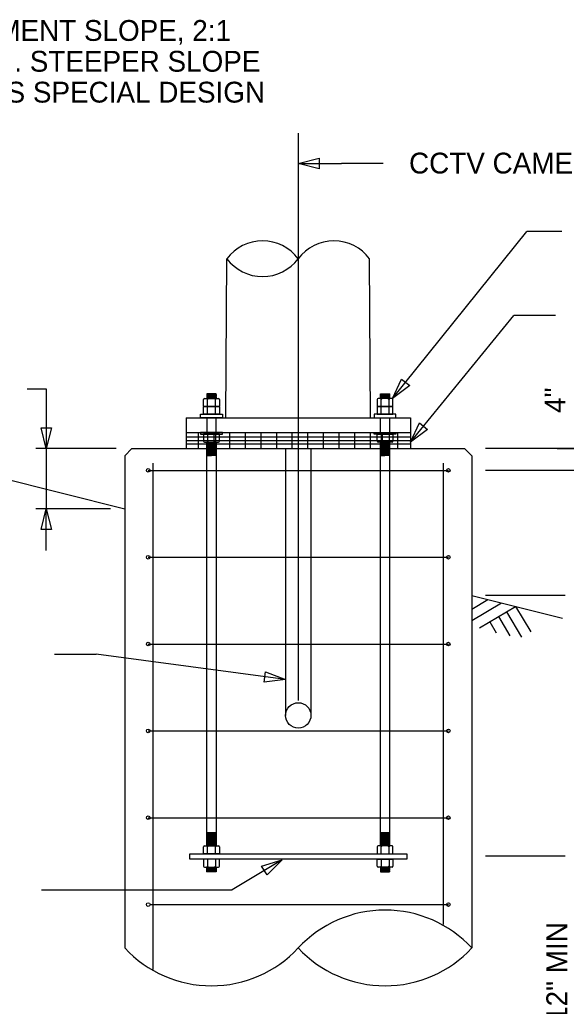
# Model space of a CAD drawing. Extents: x 1299104.6 to 1299141.4, y 239713.3 to 239735.3.
# Drawn here: x 1299108.96 to 1299112.11, y 239719.15 to 239724.83 of the extents above; entities that cross this region are included whole.
import ezdxf

# ---------------------------------------------------------------- set-up
doc = ezdxf.new("R2010")
doc.units = 0
for name, color, linetype in [('DIM TXT', 7, 'Continuous'), ('Level 3', 7, 'Continuous'), ('Level 4', 7, 'Continuous'), ('Level 7', 7, 'Continuous'), ('Level 8', 7, 'Continuous')]:
    doc.layers.add(name, color=color, linetype=linetype)

msp = doc.modelspace()

# ---------------------------------------------------------------- linework, layer by layer
at = {"layer": 'Level 3'}
for p, q in [((1299110.1458, 239722.5377), (1299110.1513, 239723.4544)), ((1299110.9791, 239722.5377), (1299110.9737, 239723.4544)), ((1299107.0626, 239722.6396), (1299109.5625, 239722.0146)), ((1299110.0397, 239722.6041), (1299110.0397, 239722.6443)), ((1299110.0853, 239722.6041), (1299110.0853, 239722.6443)), ((1299111.0397, 239722.6041), (1299111.0397, 239722.6443)), ((1299111.0853, 239722.6041), (1299111.0853, 239722.6443)), ((1299110.0397, 239722.5585), (1299110.0397, 239722.5988)), ((1299110.0853, 239722.5585), (1299110.0853, 239722.5988)), ((1299111.0397, 239722.5585), (1299111.0397, 239722.5988)), ((1299111.0853, 239722.5585), (1299111.0853, 239722.5988)), ((1299109.9166, 239722.5377), (1299111.2083, 239722.5377)), ((1299109.9166, 239722.5377), (1299109.9166, 239722.4544)), ((1299111.0884, 239722.5377), (1299111.0884, 239722.4544)), ((1299111.2083, 239722.5377), (1299111.2083, 239722.4544)), ((1299109.9166, 239722.4544), (1299111.2083, 239722.4544)), ((1299110.0397, 239722.4439), (1299110.0397, 239722.4037)), ((1299110.0853, 239722.4439), (1299110.0853, 239722.4037)), ((1299111.0397, 239722.4439), (1299111.0397, 239722.4037)), ((1299111.0853, 239722.4439), (1299111.0853, 239722.4037)), ((1299109.6041, 239722.3606), (1299109.5625, 239722.3189)), ((1299109.6041, 239722.3606), (1299111.5208, 239722.3606)), ((1299110.4896, 239722.3606), (1299110.4896, 239720.8247)), ((1299110.6354, 239722.3606), (1299110.6354, 239720.8247)), ((1299111.5208, 239722.3606), (1299111.5625, 239722.3189)), ((1299109.5625, 239722.3189), (1299109.5625, 239719.4856)), ((1299111.5625, 239722.3189), (1299111.5625, 239719.4856)), ((1299109.6979, 239722.2356), (1299111.4271, 239722.2356)), ((1299109.7265, 239719.361), (1299109.7265, 239722.2773)), ((1299111.3984, 239719.6215), (1299111.3984, 239722.2773)), ((1299109.6979, 239721.7356), (1299111.4271, 239721.7356)), ((1299111.5625, 239721.5146), (1299112.0854, 239721.3839)), ((1299109.6979, 239721.2356), (1299111.4271, 239721.2356)), ((1299109.6979, 239720.7356), (1299111.4271, 239720.7356)), ((1299109.6979, 239720.2356), (1299111.4271, 239720.2356)), ((1299110.0397, 239720.0273), (1299110.0397, 239720.0675)), ((1299110.0853, 239720.0273), (1299110.0853, 239720.0675)), ((1299111.0397, 239720.0273), (1299111.0397, 239720.0675)), ((1299111.0853, 239720.0273), (1299111.0853, 239720.0675)), ((1299109.9375, 239720.0273), (1299111.1875, 239720.0273)), ((1299109.9375, 239719.996), (1299109.9375, 239720.0273)), ((1299111.1875, 239720.0273), (1299111.1875, 239719.996)), ((1299111.1875, 239719.996), (1299109.9375, 239719.996)), ((1299110.0397, 239719.996), (1299110.0397, 239719.9558)), ((1299110.0853, 239719.996), (1299110.0853, 239719.9558)), ((1299111.0397, 239719.996), (1299111.0397, 239719.9558)), ((1299111.0853, 239719.996), (1299111.0853, 239719.9558)), ((1299109.7083, 239719.7356), (1299111.4271, 239719.7356))]:
    msp.add_line(p, q, dxfattribs=at)
for points in [[(1299110.108, 239722.6443), (1299110.108, 239722.6041), (1299110.0169, 239722.6041), (1299110.0169, 239722.6443)], [(1299110.0222, 239722.6497), (1299110.1027, 239722.6497)], [(1299110.0885, 239722.6497), (1299110.0885, 239722.6757), (1299110.0364, 239722.6757), (1299110.0364, 239722.6497)], [(1299111.0169, 239722.6443), (1299111.0169, 239722.6041), (1299111.108, 239722.6041), (1299111.108, 239722.6443)], [(1299111.1027, 239722.6497), (1299111.0222, 239722.6497)], [(1299111.0364, 239722.6497), (1299111.0364, 239722.6757), (1299111.0885, 239722.6757), (1299111.0885, 239722.6497)], [(1299110.108, 239722.5988), (1299110.108, 239722.5585), (1299110.0169, 239722.5585), (1299110.0169, 239722.5988)], [(1299110.0222, 239722.6041), (1299110.1027, 239722.6041)], [(1299111.0169, 239722.5988), (1299111.0169, 239722.5585), (1299111.108, 239722.5585), (1299111.108, 239722.5988)], [(1299111.1027, 239722.6041), (1299111.0222, 239722.6041)], [(1299110.0885, 239722.4544), (1299110.0885, 239722.5377), (1299110.0364, 239722.5377), (1299110.0364, 239722.4544)], [(1299111.0364, 239722.4544), (1299111.0364, 239722.5377), (1299111.0885, 239722.5377), (1299111.0885, 239722.4544)], [(1299110.108, 239722.4037), (1299110.108, 239722.4439), (1299110.0169, 239722.4439), (1299110.0169, 239722.4037)], [(1299110.0222, 239722.3984), (1299110.1027, 239722.3984)], [(1299110.0364, 239720.0729), (1299110.0364, 239722.3984), (1299110.0885, 239722.3984), (1299110.0885, 239720.0729)], [(1299111.0169, 239722.4037), (1299111.0169, 239722.4439), (1299111.108, 239722.4439), (1299111.108, 239722.4037)], [(1299111.1027, 239722.3984), (1299111.0222, 239722.3984)], [(1299111.0364, 239720.0729), (1299111.0364, 239722.3984), (1299111.0885, 239722.3984), (1299111.0885, 239720.0729)], [(1299110.108, 239720.0675), (1299110.108, 239720.0273), (1299110.0169, 239720.0273), (1299110.0169, 239720.0675)], [(1299110.0222, 239720.0729), (1299110.1027, 239720.0729)], [(1299111.0169, 239720.0675), (1299111.0169, 239720.0273), (1299111.108, 239720.0273), (1299111.108, 239720.0675)], [(1299111.1027, 239720.0729), (1299111.0222, 239720.0729)], [(1299110.108, 239719.9558), (1299110.108, 239719.996), (1299110.0169, 239719.996), (1299110.0169, 239719.9558)], [(1299111.0169, 239719.9558), (1299111.0169, 239719.996), (1299111.108, 239719.996), (1299111.108, 239719.9558)], [(1299110.0222, 239719.9505), (1299110.1027, 239719.9505)], [(1299110.0885, 239719.9505), (1299110.0885, 239719.9244), (1299110.0364, 239719.9244), (1299110.0364, 239719.9505)], [(1299111.1027, 239719.9505), (1299111.0222, 239719.9505)], [(1299111.0364, 239719.9505), (1299111.0364, 239719.9244), (1299111.0885, 239719.9244), (1299111.0885, 239719.9505)]]:
    msp.add_lwpolyline(points, dxfattribs=at)
for points in [[(1299110.125, 239722.5377), (1299110, 239722.5377), (1299110, 239722.5585), (1299110.125, 239722.5585)], [(1299111, 239722.5377), (1299111.125, 239722.5377), (1299111.125, 239722.5585), (1299111, 239722.5585)], [(1299110.125, 239722.4544), (1299110, 239722.4544), (1299110, 239722.4439), (1299110.125, 239722.4439)], [(1299111, 239722.4544), (1299111.125, 239722.4544), (1299111.125, 239722.4439), (1299111, 239722.4439)]]:
    msp.add_lwpolyline(points, close=True, dxfattribs=at)
for centre, radius in [((1299109.6979, 239722.2356), 0.0104), ((1299111.4271, 239722.2356), 0.0104), ((1299109.6979, 239721.7356), 0.0104), ((1299111.4271, 239721.7356), 0.0104), ((1299109.6979, 239721.2356), 0.0104), ((1299111.4271, 239721.2356), 0.0104), ((1299110.5625, 239720.8247), 0.0729), ((1299109.6979, 239720.7356), 0.0104), ((1299111.4271, 239720.7356), 0.0104), ((1299109.6979, 239720.2356), 0.0104), ((1299111.4271, 239720.2356), 0.0104), ((1299109.6979, 239719.7356), 0.0104), ((1299111.4271, 239719.7356), 0.0104)]:
    msp.add_circle(centre, radius, dxfattribs=at)
for centre, radius, start, end in [((1299110.3569, 239723.3002), 0.257, 36.8699, 143.1301), ((1299110.7681, 239723.3002), 0.257, 36.8699, 143.1301), ((1299110.3569, 239723.6086), 0.257, 216.8699, 323.1301), ((1299110.0222, 239722.6443), 0.00533, 90, 180), ((1299110.0344, 239722.6443), 0.00533, 0, 90), ((1299110.0906, 239722.6443), 0.00533, 90, 180), ((1299110.1027, 239722.6443), 0.00533, 0, 90), ((1299111.0222, 239722.6443), 0.00533, 90, 180), ((1299111.0344, 239722.6443), 0.00533, 0, 90), ((1299111.0906, 239722.6443), 0.00533, 90, 180), ((1299111.1027, 239722.6443), 0.00533, 0, 90), ((1299110.0222, 239722.5988), 0.00533, 90, 180), ((1299110.0344, 239722.5988), 0.00533, 0, 90), ((1299110.0906, 239722.5988), 0.00533, 90, 180), ((1299110.1027, 239722.5988), 0.00533, 0, 90), ((1299111.0222, 239722.5988), 0.00533, 90, 180), ((1299111.0344, 239722.5988), 0.00533, 0, 90), ((1299111.0906, 239722.5988), 0.00533, 90, 180), ((1299111.1027, 239722.5988), 0.00533, 0, 90), ((1299110.0222, 239722.4037), 0.00533, 180, 270), ((1299110.0344, 239722.4037), 0.00533, 270, 360), ((1299110.0906, 239722.4037), 0.00533, 180, 270), ((1299110.1027, 239722.4037), 0.00533, 270, 360), ((1299111.0222, 239722.4037), 0.00533, 180, 270), ((1299111.0344, 239722.4037), 0.00533, 270, 360), ((1299111.0906, 239722.4037), 0.00533, 180, 270), ((1299111.1027, 239722.4037), 0.00533, 270, 360), ((1299110.0222, 239720.0675), 0.00533, 90, 180), ((1299110.0344, 239720.0675), 0.00533, 0, 90), ((1299110.0906, 239720.0675), 0.00533, 90, 180), ((1299110.1027, 239720.0675), 0.00533, 0, 90), ((1299111.0222, 239720.0675), 0.00533, 90, 180), ((1299111.0344, 239720.0675), 0.00533, 0, 90), ((1299111.0906, 239720.0675), 0.00533, 90, 180), ((1299111.1027, 239720.0675), 0.00533, 0, 90), ((1299110.0222, 239719.9558), 0.00533, 180, 270), ((1299110.0344, 239719.9558), 0.00533, 270, 360), ((1299110.0906, 239719.9558), 0.00533, 180, 270), ((1299110.1027, 239719.9558), 0.00533, 270, 360), ((1299111.0222, 239719.9558), 0.00533, 180, 270), ((1299111.0344, 239719.9558), 0.00533, 270, 360), ((1299111.0906, 239719.9558), 0.00533, 180, 270), ((1299111.1027, 239719.9558), 0.00533, 270, 360), ((1299111.0625, 239719.0215), 0.6822, 42.8709, 137.1291), ((1299110.0625, 239719.9498), 0.6822, 222.8709, 317.1291), ((1299111.0625, 239719.9498), 0.6822, 222.8709, 317.1291)]:
    msp.add_arc(centre, radius, start, end, dxfattribs=at)
for centre, major_axis, start_param, end_param in [((1299110.0544, 239722.6443), (-0.0147, 0), 4.712389, 6.283185), ((1299110.0705, 239722.6443), (0.0147, 0), 0, 1.570796), ((1299111.0544, 239722.6443), (-0.0147, 0), 4.712389, 6.283185), ((1299111.0705, 239722.6443), (0.0147, 0), 0, 1.570796), ((1299110.0544, 239722.5988), (-0.0147, 0), 4.712389, 6.283185), ((1299110.0705, 239722.5988), (0.0147, 0), 0, 1.570796), ((1299111.0544, 239722.5988), (-0.0147, 0), 4.712389, 6.283185), ((1299111.0705, 239722.5988), (0.0147, 0), 0, 1.570796), ((1299110.0544, 239722.4037), (-0.0147, 0), 0, 1.570796), ((1299110.0705, 239722.4037), (0.0147, 0), 4.712389, 6.283185), ((1299111.0544, 239722.4037), (-0.0147, 0), 0, 1.570796), ((1299111.0705, 239722.4037), (0.0147, 0), 4.712389, 6.283185), ((1299110.0544, 239720.0675), (-0.0147, 0), 4.712389, 6.283185), ((1299110.0705, 239720.0675), (0.0147, 0), 0, 1.570796), ((1299111.0544, 239720.0675), (-0.0147, 0), 4.712389, 6.283185), ((1299111.0705, 239720.0675), (0.0147, 0), 0, 1.570796), ((1299110.0544, 239719.9558), (-0.0147, 0), 0, 1.570796), ((1299110.0705, 239719.9558), (0.0147, 0), 4.712389, 6.283185), ((1299111.0544, 239719.9558), (-0.0147, 0), 0, 1.570796), ((1299111.0705, 239719.9558), (0.0147, 0), 4.712389, 6.283185)]:
    msp.add_ellipse(centre, major_axis=major_axis, ratio=0.362172, start_param=start_param, end_param=end_param, dxfattribs=at)
at = {"layer": 'Level 4'}
for p, q in [((1299109.9166, 239722.4544), (1299109.9166, 239722.3606)), ((1299109.9862, 239722.4544), (1299109.9862, 239722.3606)), ((1299110.0762, 239722.4544), (1299110.0762, 239722.3606)), ((1299110.1662, 239722.4544), (1299110.1662, 239722.3606)), ((1299110.2562, 239722.4544), (1299110.2562, 239722.3606)), ((1299110.3462, 239722.4544), (1299110.3462, 239722.3606)), ((1299110.4362, 239722.4544), (1299110.4362, 239722.3606)), ((1299110.5262, 239722.4544), (1299110.5262, 239722.3606)), ((1299110.6162, 239722.4544), (1299110.6162, 239722.3606)), ((1299110.7062, 239722.4544), (1299110.7062, 239722.3606)), ((1299110.7962, 239722.4544), (1299110.7962, 239722.3606)), ((1299110.8862, 239722.4544), (1299110.8862, 239722.3606)), ((1299110.9762, 239722.4544), (1299110.9762, 239722.3606)), ((1299111.0449, 239722.4544), (1299111.0449, 239722.3606)), ((1299111.1349, 239722.4544), (1299111.1349, 239722.3606)), ((1299111.2083, 239722.4544), (1299111.2083, 239722.3606)), ((1299109.9166, 239722.4279), (1299111.2083, 239722.4279)), ((1299109.9166, 239722.4079), (1299111.2083, 239722.4079)), ((1299109.9166, 239722.3879), (1299111.2083, 239722.3879))]:
    msp.add_line(p, q, dxfattribs=at)
for points in [[(1299110.0364, 239722.6757), (1299110.0885, 239722.6757), (1299110.0364, 239722.6731), (1299110.0364, 239722.6705), (1299110.0885, 239722.6731), (1299110.0885, 239722.6705), (1299110.0364, 239722.6679), (1299110.0364, 239722.6653), (1299110.0885, 239722.6679), (1299110.0885, 239722.6653), (1299110.0364, 239722.6627), (1299110.0364, 239722.6601), (1299110.0885, 239722.6627), (1299110.0885, 239722.6601), (1299110.0364, 239722.6575), (1299110.0364, 239722.6549), (1299110.0885, 239722.6575), (1299110.0885, 239722.6549), (1299110.0364, 239722.6523), (1299110.0364, 239722.6497), (1299110.0885, 239722.6523), (1299110.0885, 239722.6497)], [(1299111.0364, 239722.6757), (1299111.0885, 239722.6757), (1299111.0364, 239722.6731), (1299111.0364, 239722.6705), (1299111.0885, 239722.6731), (1299111.0885, 239722.6705), (1299111.0364, 239722.6679), (1299111.0364, 239722.6653), (1299111.0885, 239722.6679), (1299111.0885, 239722.6653), (1299111.0364, 239722.6627), (1299111.0364, 239722.6601), (1299111.0885, 239722.6627), (1299111.0885, 239722.6601), (1299111.0364, 239722.6575), (1299111.0364, 239722.6549), (1299111.0885, 239722.6575), (1299111.0885, 239722.6549), (1299111.0364, 239722.6523), (1299111.0364, 239722.6497), (1299111.0885, 239722.6523), (1299111.0885, 239722.6497)], [(1299110.0364, 239722.3984), (1299110.0885, 239722.3984), (1299110.0364, 239722.3958), (1299110.0364, 239722.3932), (1299110.0885, 239722.3958), (1299110.0885, 239722.3932), (1299110.0364, 239722.3906), (1299110.0364, 239722.388), (1299110.0885, 239722.3906), (1299110.0885, 239722.388), (1299110.0364, 239722.3854), (1299110.0364, 239722.3827), (1299110.0885, 239722.3854), (1299110.0885, 239722.3827), (1299110.0364, 239722.3801), (1299110.0364, 239722.3775), (1299110.0885, 239722.3801), (1299110.0885, 239722.3775), (1299110.0364, 239722.3749), (1299110.0364, 239722.3723), (1299110.0885, 239722.3749), (1299110.0885, 239722.3723)], [(1299111.0364, 239722.3984), (1299111.0885, 239722.3984), (1299111.0364, 239722.3958), (1299111.0364, 239722.3932), (1299111.0885, 239722.3958), (1299111.0885, 239722.3932), (1299111.0364, 239722.3906), (1299111.0364, 239722.388), (1299111.0885, 239722.3906), (1299111.0885, 239722.388), (1299111.0364, 239722.3854), (1299111.0364, 239722.3827), (1299111.0885, 239722.3854), (1299111.0885, 239722.3827), (1299111.0364, 239722.3801), (1299111.0364, 239722.3775), (1299111.0885, 239722.3801), (1299111.0885, 239722.3775), (1299111.0364, 239722.3749), (1299111.0364, 239722.3723), (1299111.0885, 239722.3749), (1299111.0885, 239722.3723)], [(1299110.0885, 239722.3723), (1299110.0364, 239722.3697), (1299110.0364, 239722.3671), (1299110.0885, 239722.3697), (1299110.0885, 239722.3671), (1299110.0364, 239722.3645), (1299110.0364, 239722.3619), (1299110.0885, 239722.3645), (1299110.0885, 239722.3619), (1299110.0364, 239722.3593), (1299110.0364, 239722.3567), (1299110.0885, 239722.3593), (1299110.0885, 239722.3567), (1299110.0364, 239722.3541), (1299110.0364, 239722.3515), (1299110.0885, 239722.3541), (1299110.0885, 239722.3515), (1299110.0364, 239722.3489), (1299110.0364, 239722.3463), (1299110.0885, 239722.3489), (1299110.0885, 239722.3463)], [(1299110.0885, 239722.3463), (1299110.0364, 239722.3437), (1299110.0364, 239722.3411), (1299110.0885, 239722.3437), (1299110.0885, 239722.3411), (1299110.0364, 239722.3385), (1299110.0364, 239722.3359), (1299110.0885, 239722.3385), (1299110.0885, 239722.3359), (1299110.0364, 239722.3333), (1299110.0364, 239722.3307), (1299110.0885, 239722.3333), (1299110.0885, 239722.3307), (1299110.0364, 239722.3281), (1299110.0364, 239722.3255), (1299110.0885, 239722.3281), (1299110.0885, 239722.3255), (1299110.0364, 239722.3229), (1299110.0364, 239722.3202), (1299110.0885, 239722.3229), (1299110.0885, 239722.3202)], [(1299111.0885, 239722.3723), (1299111.0364, 239722.3697), (1299111.0364, 239722.3671), (1299111.0885, 239722.3697), (1299111.0885, 239722.3671), (1299111.0364, 239722.3645), (1299111.0364, 239722.3619), (1299111.0885, 239722.3645), (1299111.0885, 239722.3619), (1299111.0364, 239722.3593), (1299111.0364, 239722.3567), (1299111.0885, 239722.3593), (1299111.0885, 239722.3567), (1299111.0364, 239722.3541), (1299111.0364, 239722.3515), (1299111.0885, 239722.3541), (1299111.0885, 239722.3515), (1299111.0364, 239722.3489), (1299111.0364, 239722.3463), (1299111.0885, 239722.3489), (1299111.0885, 239722.3463)], [(1299111.0885, 239722.3463), (1299111.0364, 239722.3437), (1299111.0364, 239722.3411), (1299111.0885, 239722.3437), (1299111.0885, 239722.3411), (1299111.0364, 239722.3385), (1299111.0364, 239722.3359), (1299111.0885, 239722.3385), (1299111.0885, 239722.3359), (1299111.0364, 239722.3333), (1299111.0364, 239722.3307), (1299111.0885, 239722.3333), (1299111.0885, 239722.3307), (1299111.0364, 239722.3281), (1299111.0364, 239722.3255), (1299111.0885, 239722.3281), (1299111.0885, 239722.3255), (1299111.0364, 239722.3229), (1299111.0364, 239722.3202), (1299111.0885, 239722.3229), (1299111.0885, 239722.3202)], [(1299110.0885, 239720.151), (1299110.0364, 239720.1484), (1299110.0364, 239720.1458), (1299110.0885, 239720.1484), (1299110.0885, 239720.1458), (1299110.0364, 239720.1432), (1299110.0364, 239720.1406), (1299110.0885, 239720.1432), (1299110.0885, 239720.1406), (1299110.0364, 239720.138), (1299110.0364, 239720.1354), (1299110.0885, 239720.138), (1299110.0885, 239720.1354), (1299110.0364, 239720.1327), (1299110.0364, 239720.1301), (1299110.0885, 239720.1327), (1299110.0885, 239720.1301), (1299110.0364, 239720.1275), (1299110.0364, 239720.1249), (1299110.0885, 239720.1275), (1299110.0885, 239720.1249)], [(1299110.0885, 239720.1249), (1299110.0364, 239720.1223), (1299110.0364, 239720.1197), (1299110.0885, 239720.1223), (1299110.0885, 239720.1197), (1299110.0364, 239720.1171), (1299110.0364, 239720.1145), (1299110.0885, 239720.1171), (1299110.0885, 239720.1145), (1299110.0364, 239720.1119), (1299110.0364, 239720.1093), (1299110.0885, 239720.1119), (1299110.0885, 239720.1093), (1299110.0364, 239720.1067), (1299110.0364, 239720.1041), (1299110.0885, 239720.1067), (1299110.0885, 239720.1041), (1299110.0364, 239720.1015), (1299110.0364, 239720.0989), (1299110.0885, 239720.1015), (1299110.0885, 239720.0989)], [(1299111.0885, 239720.151), (1299111.0364, 239720.1484), (1299111.0364, 239720.1458), (1299111.0885, 239720.1484), (1299111.0885, 239720.1458), (1299111.0364, 239720.1432), (1299111.0364, 239720.1406), (1299111.0885, 239720.1432), (1299111.0885, 239720.1406), (1299111.0364, 239720.138), (1299111.0364, 239720.1354), (1299111.0885, 239720.138), (1299111.0885, 239720.1354), (1299111.0364, 239720.1327), (1299111.0364, 239720.1301), (1299111.0885, 239720.1327), (1299111.0885, 239720.1301), (1299111.0364, 239720.1275), (1299111.0364, 239720.1249), (1299111.0885, 239720.1275), (1299111.0885, 239720.1249)], [(1299111.0885, 239720.1249), (1299111.0364, 239720.1223), (1299111.0364, 239720.1197), (1299111.0885, 239720.1223), (1299111.0885, 239720.1197), (1299111.0364, 239720.1171), (1299111.0364, 239720.1145), (1299111.0885, 239720.1171), (1299111.0885, 239720.1145), (1299111.0364, 239720.1119), (1299111.0364, 239720.1093), (1299111.0885, 239720.1119), (1299111.0885, 239720.1093), (1299111.0364, 239720.1067), (1299111.0364, 239720.1041), (1299111.0885, 239720.1067), (1299111.0885, 239720.1041), (1299111.0364, 239720.1015), (1299111.0364, 239720.0989), (1299111.0885, 239720.1015), (1299111.0885, 239720.0989)], [(1299110.0885, 239720.0989), (1299110.0364, 239720.0963), (1299110.0364, 239720.0937), (1299110.0885, 239720.0963), (1299110.0885, 239720.0937), (1299110.0364, 239720.0911), (1299110.0364, 239720.0885), (1299110.0885, 239720.0911), (1299110.0885, 239720.0885), (1299110.0364, 239720.0859), (1299110.0364, 239720.0833), (1299110.0885, 239720.0859), (1299110.0885, 239720.0833), (1299110.0364, 239720.0807), (1299110.0364, 239720.0781), (1299110.0885, 239720.0807), (1299110.0885, 239720.0781), (1299110.0364, 239720.0755), (1299110.0364, 239720.0729), (1299110.0885, 239720.0755), (1299110.0885, 239720.0729)], [(1299111.0885, 239720.0989), (1299111.0364, 239720.0963), (1299111.0364, 239720.0937), (1299111.0885, 239720.0963), (1299111.0885, 239720.0937), (1299111.0364, 239720.0911), (1299111.0364, 239720.0885), (1299111.0885, 239720.0911), (1299111.0885, 239720.0885), (1299111.0364, 239720.0859), (1299111.0364, 239720.0833), (1299111.0885, 239720.0859), (1299111.0885, 239720.0833), (1299111.0364, 239720.0807), (1299111.0364, 239720.0781), (1299111.0885, 239720.0807), (1299111.0885, 239720.0781), (1299111.0364, 239720.0755), (1299111.0364, 239720.0729), (1299111.0885, 239720.0755), (1299111.0885, 239720.0729)], [(1299110.0364, 239719.9505), (1299110.0885, 239719.9505), (1299110.0364, 239719.9479), (1299110.0364, 239719.9452), (1299110.0885, 239719.9479), (1299110.0885, 239719.9452), (1299110.0364, 239719.9426), (1299110.0364, 239719.94), (1299110.0885, 239719.9426), (1299110.0885, 239719.94), (1299110.0364, 239719.9374), (1299110.0364, 239719.9348), (1299110.0885, 239719.9374), (1299110.0885, 239719.9348), (1299110.0364, 239719.9322), (1299110.0364, 239719.9296), (1299110.0885, 239719.9322), (1299110.0885, 239719.9296), (1299110.0364, 239719.927), (1299110.0364, 239719.9244), (1299110.0885, 239719.927), (1299110.0885, 239719.9244)], [(1299111.0364, 239719.9505), (1299111.0885, 239719.9505), (1299111.0364, 239719.9479), (1299111.0364, 239719.9452), (1299111.0885, 239719.9479), (1299111.0885, 239719.9452), (1299111.0364, 239719.9426), (1299111.0364, 239719.94), (1299111.0885, 239719.9426), (1299111.0885, 239719.94), (1299111.0364, 239719.9374), (1299111.0364, 239719.9348), (1299111.0885, 239719.9374), (1299111.0885, 239719.9348), (1299111.0364, 239719.9322), (1299111.0364, 239719.9296), (1299111.0885, 239719.9322), (1299111.0885, 239719.9296), (1299111.0364, 239719.927), (1299111.0364, 239719.9244), (1299111.0885, 239719.927), (1299111.0885, 239719.9244)]]:
    msp.add_lwpolyline(points, dxfattribs=at)
at = {"layer": 'Level 7'}
msp.add_line((1299110.5625, 239724.1769), (1299110.5625, 239720.9111), dxfattribs=at)
at = {"layer": 'Level 8'}
for p, q in [((1299110.5625, 239724.0025), (1299110.8125, 239724.0025)), ((1299111.0525, 239724.0025), (1299110.8125, 239724.0025)), ((1299111.1061, 239722.6485), (1299111.8795, 239723.6111)), ((1299112.0813, 239723.6111), (1299111.8795, 239723.6111)), ((1299111.2083, 239722.3974), (1299111.8037, 239723.1279)), ((1299111.2083, 239722.3974), (1299111.8037, 239723.1279)), ((1299112.0437, 239723.1279), (1299111.8037, 239723.1279)), ((1299109.0012, 239722.7046), (1299109.1103, 239722.7046)), ((1299109.1103, 239722.7046), (1299109.1103, 239722.3606)), ((1299109.5139, 239722.3606), (1299109.0503, 239722.3606)), ((1299109.1103, 239722.3606), (1299109.1103, 239722.0146)), ((1299113.2721, 239722.3606), (1299111.6408, 239722.3606)), ((1299112.0547, 239722.3606), (1299112.8979, 239722.3606)), ((1299112.2238, 239722.2356), (1299111.6408, 239722.2356)), ((1299109.4801, 239722.0146), (1299109.0503, 239722.0146)), ((1299109.1103, 239721.7746), (1299109.1103, 239722.0146)), ((1299111.5625, 239721.4372), (1299111.6541, 239721.4917)), ((1299112.1007, 239721.5146), (1299111.6408, 239721.5146)), ((1299111.5625, 239721.3707), (1299111.7328, 239721.4721)), ((1299111.606, 239721.3279), (1299111.8141, 239721.4517)), ((1299111.815, 239721.4515), (1299111.9019, 239721.3054)), ((1299111.7165, 239721.3937), (1299111.7822, 239721.2831)), ((1299111.7616, 239721.4205), (1299111.8482, 239721.275)), ((1299111.6658, 239721.3634), (1299111.7033, 239721.3003)), ((1299109.1586, 239721.1766), (1299109.3986, 239721.1766)), ((1299110.4896, 239721.0306), (1299109.3986, 239721.1766)), ((1299112.1007, 239720.0146), (1299111.6408, 239720.0146)), ((1299110.4697, 239719.9935), (1299110.1815, 239719.8199)), ((1299109.0838, 239719.8199), (1299110.1815, 239719.8199))]:
    msp.add_line(p, q, dxfattribs=at)
for points in [[(1299110.6825, 239723.9725), (1299110.5625, 239724.0025), (1299110.6825, 239724.0325)], [(1299111.2046, 239722.7233), (1299111.1061, 239722.6485), (1299111.1578, 239722.7608)], [(1299111.3075, 239722.4713), (1299111.2083, 239722.3974), (1299111.261, 239722.5093)], [(1299109.1403, 239722.4806), (1299109.1103, 239722.3606), (1299109.0803, 239722.4806)], [(1299109.0803, 239721.8946), (1299109.1103, 239722.0146), (1299109.1403, 239721.8946)], [(1299110.3746, 239721.0763), (1299110.4896, 239721.0306), (1299110.3666, 239721.0168)], [(1299110.3515, 239719.9573), (1299110.4697, 239719.9935), (1299110.3824, 239719.9059)]]:
    msp.add_lwpolyline(points, close=True, dxfattribs=at)

# ---------------------------------------------------------------- texts
at = {"layer": 'DIM TXT'}
for s, p in [('EMBANKMENT SLOPE, 2:1', (1299108.1508, 239724.7086)), ('MAXIMUM. STEEPER SLOPE', (1299108.1508, 239724.531)), ('REQUIRES SPECIAL DESIGN', (1299108.1508, 239724.3533)), ('  CCTV CAMERA POLE AND   DRILLED CAISSON', (1299111.1115, 239723.9449))]:
    msp.add_text(s, height=0.12, dxfattribs=at).set_placement(p)
for s, p in [('4"', (1299112.1015, 239722.5665)), ('#4@12" MIN', (1299112.1118, 239718.7184))]:
    msp.add_text(s, height=0.12, rotation=90, dxfattribs=at).set_placement(p)

doc.saveas('drawing.dxf')
